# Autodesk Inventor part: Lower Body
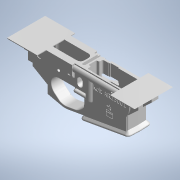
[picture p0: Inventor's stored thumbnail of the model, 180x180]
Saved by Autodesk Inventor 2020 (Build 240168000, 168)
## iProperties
Created: 2013-05
Part Number: Lower Body
Material: Generic
Document SubType Name: Modeling
Designer: johne
Appearance: Generic
Sending System: ACIS
Title: C:\Documents and Settings\Administrator\My Documents\AR-15 - Lower Receiver V5.1gs_main.STEP.stp
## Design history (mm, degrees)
feature "Base1"
sketch "Sketch1"
  geometry: L1 (0.067, -1.29)-(49.474, -1.29); L2 (49.474, -1.29)-(49.474, -38.649); L3 (49.474, -38.649)-(0.067, -38.649); L4 (0.067, -38.649)-(0.067, -1.29); L5 (49.818, 14.031)-(58.708, 14.031); L6 (58.708, 14.031)-(58.708, 4.735); C1 r 3.175 at (58.708, 4.735)
  constraints: 4 end point, 1 centre point, 1 coincident, 1 horizontal, 1 perpendicular, 2 other
  dimensions: "d0" = 6.35 diameter of C1
extrude "Extrusion1" cut sketch "Sketch1" distance "d1" = 50.8; taper "d2" = 0 deg
sketch "Sketch2"
  geometry: L1 (0.067, -1.29)-(49.474, -1.29); L2 (49.474, -1.29)-(49.474, -38.649); L3 (49.474, -38.649)-(0.067, -38.649); L4 (0.067, -38.649)-(0.067, -1.29); L5 (49.818, 14.031)-(58.708, 14.031); L6 (58.708, 14.031)-(58.708, 4.735); C1 r 3.175 at (58.708, 4.735); 1 further point
  constraints: 4 end point, 1 centre point, 1 coincident, 1 horizontal, 1 perpendicular, 2 other
  dimensions: "d3" = 6.35 diameter of C1
extrude "Extrusion2" cut sketch "Sketch2" distance "d4" = 0.508; taper "d5" = 0 deg
sketch "Sketch3"
  geometry: L1 (0.083, 0.318)-(7.097, 0.318) reference; L2 (0.083, 0.318)-(15.323, 0.319); L3 (15.323, 0.319)-(15.323, -13.778); L4 (-1.74, -48.939)-(-1.74, -29.698) reference; L5 (15.323, -13.778)-(-1.74, -29.698); L6 (-1.74, -29.698)-(0.083, 0.318); C1 r 3.175 at (7.097, -6.045) reference; 1 further point
  constraints: 8 end point, 1 vertical
  dimensions: "d6" = 15.24 distance of L1.start L2.end; "d7" = 14.097 distance of L2.end L3.end
extrude "Extrusion3" join sketch "Sketch3" stored distance "d8" = 0.508; taper "d9" = 0 deg
sketch "Sketch5"
  geometry: L1 (6.987, 0.318)-(-8.253, 0.319) reference; L2 (-8.253, 0.319)-(-8.253, -13.778) reference; L3 (-8.253, -13.778)-(6.645, -27.678) reference; L4 (9.518, -48.986)-(9.518, 0.318) reference; L5 (9.518, 0.318)-(-8.253, 0.319); L6 (-8.253, 0.319)-(-8.253, -13.778) reference; L7 (-8.253, -13.778)-(10.788, -31.542); L8 (10.788, 0.318)-(10.788, -50.5) reference; L9 (10.788, -31.542)-(10.788, 0.318); L10 (10.788, 0.318)-(-8.253, 0.319); L11 (6.324, -26.023)-(6.324, 0.318) reference; L12 (6.987, 0.318)-(6.324, 0.318) reference; L13 (6.987, 0.318)-(-8.253, 0.319) reference; L14 (-8.253, 0.319)-(-8.253, -13.778) reference; L15 (-8.253, -13.778)-(6.645, -27.678) reference; L16 (6.645, -26.562)-(6.645, -27.678) reference; L17 (6.324, -26.023)-(6.645, -26.562) reference; L18 (6.324, 0.318)-(6.324, -27.378); L19 (6.324, -47.042)-(6.324, -26.023) reference; C1 r 3.175 at (-0.026, -6.045) reference; C2 r 3.175 at (-0.026, -6.045) reference; 1 further point
  constraints: 10 end point, 2 point on line, 1 parallel
extrude "Extrusion4" join sketch "Sketch5" stored distance "d10" = 0.508; taper "d11" = 0 deg
sketch "Sketch7"
  geometry: L1 (-0.686, 21.608)-(-8.623, 21.608) reference; L2 (1.27, 49.304)-(-0.686, 49.304); L3 (-0.686, 49.304)-(-0.686, 21.608); L4 (-0.686, 21.608)-(1.27, 21.608); L5 (1.27, 21.608)-(1.27, 49.304); 1 further point
  constraints: 8 end point, 2 parallel, 1 horizontal, 1 perpendicular
extrude "Extrusion5" join sketch "Sketch7" stored distance "d12" = 0.508; taper "d13" = 0 deg
sketch "Sketch8"
  geometry: L1 (79.678, 27.031)-(75.901, 27.031); L2 (75.901, 27.031)-(75.901, 28.845); L3 (75.901, 28.845)-(79.678, 28.845); L4 (79.678, 28.845)-(79.678, 27.031); 1 further point
  constraints: 8 end point, 2 parallel, 1 horizontal, 1 perpendicular
extrude "Extrusion6" join sketch "Sketch8" distance "d14" = 0.508; taper "d15" = 0 deg
sketch "Sketch9"
  geometry: L1 (0, 21.608)-(0, 49.304) reference; L2 (0, 49.304)-(-1.27, 49.304) reference; L3 (-1.27, 49.304)-(-1.27, 21.608) reference; L4 (-1.27, 21.608)-(0, 21.608) reference; 1 further point
extrude "Extrusion7" join sketch "Sketch9" distance "d16" = 2.54; taper "d17" = 0 deg
sketch "Sketch10"
  geometry: L1 (14.577, 13.6)-(0, 0) reference; L2 (0, 0)-(14.577, 0) reference; L3 (14.577, 0)-(14.577, 13.6) reference; C1 r 3.175 at (6.35, 21.333) reference; 1 further point
extrude "Extrusion8" cut sketch "Sketch10" distance "d18" = 25.4; taper "d19" = 0 deg
fillet "Fillet1" dims "d20" = 1.27
sketch "Sketch11"
  geometry: L1 (0, 0)-(2.388, 0) reference; L2 (2.388, 0)-(2.388, 4.596) reference; L3 (2.388, 4.596)-(0, 4.596) reference; L4 (0, 0)-(0, 4.596) reference; L5 (9.523, 4.596)-(-5.763, 4.596) reference; L6 (6.149, -5.364)-(-3.569, -5.364); L7 (-3.569, -5.364)-(-3.569, 4.596); L8 (-3.569, 4.596)-(6.149, 4.596); L9 (6.149, 4.596)-(6.149, -5.364); 1 further point
  constraints: 8 end point, 2 parallel, 1 horizontal, 1 perpendicular, 1 point on line
extrude "Extrusion9" cut sketch "Sketch11" distance "d21" = 2.54; taper "d22" = 0 deg
sketch "Sketch12"
  geometry: L1 (33.211, 0.39)-(47.71, 0.39); L2 (47.71, 0.39)-(47.71, -9.066); L3 (47.71, -9.066)-(33.211, -9.066); L4 (33.211, -9.066)-(33.211, 0.39); L5 (31.497, -1.711)-(45.904, -1.711); L6 (45.904, -1.711)-(45.904, -7.52); L7 (45.904, -7.52)-(31.497, -7.52); L8 (31.497, -7.52)-(31.497, -1.711); 1 further point
  constraints: 8 end point, 2 parallel, 1 horizontal, 1 perpendicular, 2 other
extrude "Extrusion10" join sketch "Sketch12" distance "d23" = 1.016; taper "d24" = 0 deg
sketch "Sketch13"
  geometry: L1 (45.501, -1.483)-(67.918, -1.483); L2 (67.918, -1.483)-(67.918, -7.773); L3 (67.918, -7.773)-(45.501, -7.773); L4 (45.501, -7.773)-(45.501, -1.483); A1 r 10.362 centre (55.663, -18.136) between (64.101, -12.12) and (47.226, -12.12) reference; 1 further point
  constraints: 8 end point, 2 parallel, 1 horizontal, 1 perpendicular
extrude "Extrusion11" join sketch "Sketch13" distance "d25" = 1.016; taper "d26" = 0 deg
sketch "Sketch14"
  geometry: L1 (30.031, -0.213)-(52.828, -0.213); L2 (52.828, -0.213)-(52.828, -7.716); L3 (52.828, -7.716)-(30.031, -7.716); L4 (30.031, -7.716)-(30.031, -0.213); 1 further point
  constraints: 2 other
sketch "Sketch15"
  geometry: L1 (44.289, -4.551)-(70.126, -4.551); L2 (70.126, -4.551)-(70.126, -9.234); L3 (70.126, -9.234)-(44.289, -9.234); L4 (44.289, -9.234)-(44.289, -4.551); A1 r 10.362 centre (55.663, -18.136) between (64.101, -12.12) and (47.226, -12.12) reference; 1 further point
  constraints: 2 other
extrude "Extrusion12" cut sketch "Sketch14" distance "d27" = 1.016; taper "d28" = 0 deg
extrude "Extrusion13" cut sketch "Sketch15" distance "d29" = 1.016; taper "d30" = 0 deg
sketch "Sketch16"
  geometry: L1 (18.123, 4.596)-(-2.134, 4.596) reference; L2 (-2.134, 4.596)-(8.974, 4.596); L3 (8.974, 4.596)-(8.974, -7.604); L4 (8.974, -7.604)-(-2.134, -7.604); L5 (-2.134, -7.604)-(-2.134, 4.596); 1 further point
  constraints: 8 end point, 2 parallel, 1 horizontal, 1 perpendicular
extrude "Extrusion14" cut sketch "Sketch16" stored distance "d31" = 1.016; taper "d32" = 0 deg
sketch "Sketch19"
  geometry: L1 (0.426, -10.923)-(49.548, -10.923); L2 (49.548, -10.923)-(49.548, -43.999); L3 (49.548, -43.999)-(0.426, -43.999); L4 (0.426, -43.999)-(0.426, -10.923); L5 (20.374, -24.214)-(24.084, -24.214); L6 (24.084, -24.214)-(24.852, -25.164); L7 (24.852, -25.164)-(29.633, -25.164); L8 (29.633, -31.769)-(20.374, -31.769); L9 (23.426, -21.87)-(24.04, -19.818); L10 (24.418, -18.549)-(25.032, -16.496); L11 (22.277, -18.6)-(24.418, -18.549); L12 (25.742, -18.517)-(27.884, -18.466); L13 (26.892, -21.788)-(26.181, -19.766); L14 (25.742, -18.517)-(25.032, -16.496); L15 (27.884, -18.466)-(26.181, -19.766); L16 (25.129, -20.57)-(23.426, -21.87); L17 (26.892, -21.788)-(25.129, -20.57); L18 (24.04, -19.818)-(22.277, -18.6); L19 (25.002, -15.264)-(24.133, -18.175); L20 (24.133, -18.175)-(21.095, -18.247); L21 (21.095, -18.247)-(23.595, -19.974); L22 (23.595, -19.974)-(22.726, -22.885); L23 (22.726, -22.885)-(25.14, -21.041); L24 (25.14, -21.041)-(27.64, -22.767); L25 (27.64, -22.767)-(26.632, -19.901); L26 (26.632, -19.901)-(29.047, -18.057); L27 (29.047, -18.057)-(26.01, -18.13); L28 (26.01, -18.13)-(25.002, -15.264); L29 (30.014, -24.783)-(25.034, -24.783); L30 (25.034, -24.783)-(24.266, -23.833); L31 (24.266, -23.833)-(19.993, -23.833); L32 (19.993, -23.833)-(19.993, -32.15); L33 (19.993, -32.15)-(30.014, -32.15); L34 (30.014, -32.15)-(30.014, -24.783); L35 (20.374, -26.98)-(29.633, -26.98); L36 (29.633, -26.467)-(20.374, -26.467); L37 (29.633, -25.164)-(29.633, -26.467); L38 (29.633, -26.98)-(29.633, -31.769); L39 (20.374, -31.769)-(20.374, -26.98); L40 (20.374, -26.467)-(20.374, -24.214); 2 further points; 1 other entity
  constraints: 72 end point, 9 perpendicular, 3 parallel, 2 vertical, 1 horizontal, 19 other
  dimensions: "d152" = 0.381 distance between parallel lines of L14 L28; "d153" = 0.381 distance between parallel lines of L7 L29
extrude "Extrusion15" cut sketch "Sketch19" distance "d156" = 0.508; taper "d157" = 0 deg
sketch "Sketch20"
  geometry: L1 (-68.913, 58.342)-(-68.913, 45.515) reference; L2 (-68.913, 45.515)-(-54.337, 31.916) reference; L3 (-54.337, 31.916)-(-49.873, 31.916) reference; L4 (-49.873, 31.916)-(-49.873, 8.794) reference; L5 (0, 0)-(-49.873, 8.794) reference; L6 (0, 0)-(0, 35.799) reference; L7 (-1.657, 35.799)-(0, 35.799) reference; L8 (-1.657, 42.149)-(0, 42.149) reference; L9 (0, 42.149)-(0, 52.114) reference; L10 (0, 52.114)-(-2.483, 52.114) reference; L11 (-2.483, 52.114)-(-2.483, 56.804) reference; L12 (-2.483, 56.804)-(0, 56.804) reference; L13 (0, 56.804)-(0, 59.611) reference; L14 (0, 59.611)-(-67.694, 59.611) reference; L15 (-16.347, 26.543)-(-17.331, 26.543) reference; L16 (-17.331, 26.543)-(-17.331, 29.718) reference; L17 (-17.331, 29.718)-(-16.69, 29.718) reference; L18 (-21.157, 29.393)-(-21.849, 29.393) reference; L19 (-21.849, 29.393)-(-21.849, 29.718) reference; L20 (-21.849, 29.718)-(-20.18, 29.718) reference; L21 (-20.18, 29.718)-(-20.18, 29.393) reference; L22 (-20.18, 29.393)-(-20.872, 29.393) reference; L23 (-20.872, 29.393)-(-20.872, 26.543) reference; L24 (-20.872, 26.543)-(-21.157, 26.543) reference; L25 (-21.157, 26.543)-(-21.157, 29.393) reference; L26 (-26.856, 26.543)-(-26.856, 29.718) reference; L27 (-26.856, 29.718)-(-26.236, 29.718) reference; L28 (-25.997, 26.543)-(-26.856, 26.543) reference; L29 (-30.641, 26.543)-(-30.641, 29.718) reference; L30 (-30.641, 29.718)-(-30.006, 29.718) reference; L31 (-29.773, 28.009)-(-28.606, 26.543) reference; L32 (-28.606, 26.543)-(-28.958, 26.543) reference; L33 (-28.958, 26.543)-(-30.125, 28.009) reference; L34 (-30.125, 28.009)-(-30.356, 28.009) reference; L35 (-30.356, 28.009)-(-30.356, 26.543) reference; L36 (-30.356, 26.543)-(-30.641, 26.543) reference; L37 (-34.956, 27.156)-(-34.688, 27.317) reference; L38 (-33.124, 29.262)-(-33.382, 29.067) reference; L39 (-38.002, 26.543)-(-38.986, 26.543) reference; L40 (-38.986, 26.543)-(-38.986, 29.718) reference; L41 (-38.986, 29.718)-(-38.345, 29.718) reference; L42 (-25.96, 33.447)-(-25.692, 33.608) reference; L43 (-24.129, 35.554)-(-24.386, 35.359) reference; L44 (-31.252, 32.835)-(-31.252, 36.01) reference; L45 (-31.252, 36.01)-(-29.461, 36.01) reference; L46 (-29.461, 36.01)-(-29.461, 35.684) reference; L47 (-29.461, 35.684)-(-30.967, 35.684) reference; L48 (-30.967, 35.684)-(-30.967, 34.707) reference; L49 (-30.967, 34.707)-(-29.461, 34.707) reference; L50 (-29.461, 34.707)-(-29.461, 34.382) reference; L51 (-29.461, 34.382)-(-30.967, 34.382) reference; L52 (-30.967, 34.382)-(-30.967, 33.161) reference; L53 (-30.967, 33.161)-(-29.461, 33.161) reference; L54 (-29.461, 33.161)-(-29.461, 32.835) reference; L55 (-29.461, 32.835)-(-31.252, 32.835) reference; L56 (-35.73, 32.835)-(-35.73, 36.01) reference; L57 (-35.73, 36.01)-(-33.939, 36.01) reference; L58 (-33.939, 36.01)-(-33.939, 35.684) reference; L59 (-33.939, 35.684)-(-35.445, 35.684) reference; L60 (-35.445, 35.684)-(-35.445, 34.707) reference; L61 (-35.445, 34.707)-(-33.939, 34.707) reference; L62 (-33.939, 34.707)-(-33.939, 34.382) reference; L63 (-33.939, 34.382)-(-35.445, 34.382) reference; L64 (-35.445, 34.382)-(-35.445, 33.161) reference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; C1 r 3.175 at (-60.687, 53.248) reference; C2 r 1.5 at (-60.687, 53.248); A1 r 1.27 centre (-67.643, 58.342) between (-67.694, 59.611) and (-68.913, 58.342) reference; A2 r 6.35 centre (-7.156, 38.974) between (-12.864, 36.191) and (-1.657, 35.799) reference; A3 r 3.175 centre (-11.335, 38.974) between (-12.864, 41.756) and (-12.864, 36.191) reference; A4 r 6.35 centre (-7.156, 38.974) between (-1.657, 42.149) and (-12.864, 41.756) reference; 44 further points
  constraints: 1 centre point, 1 coincident, 53 other
  dimensions: "d162" = 3 diameter of C2
  node "Projected Loop10"
sketch "Sketch21"
  geometry: L1 (0.083, 1.587)-(14.053, 1.588) reference; L2 (0.064, 1.27)-(0.083, 1.587) reference; L3 (0.064, 1.27)-(0, 1.27) reference; L4 (0, 1.27)-(0, 0) reference; L5 (0, 0)-(3.352, 0) reference; L6 (3.414, -0.166)-(3.414, -13.807) reference; L7 (0, -26.005)-(0.1, -25.838) reference; L8 (0, -26.805)-(0, -26.005) reference; L9 (15.323, -12.508)-(0, -26.805) reference; L10 (15.323, 0.318)-(15.323, -12.508) reference; C1 r 3.175 at (7.097, -4.775) reference; C2 r 1.5 at (7.097, -4.775); A1 r 1.27 centre (14.053, 0.318) between (15.323, 0.318) and (14.053, 1.588) reference; A2 r 0.254 centre (3.16, -0.166) between (3.414, -0.166) and (3.352, 0) reference; A3 r 23.495 centre (-20.081, -13.807) between (0.1, -25.838) and (3.414, -13.807) reference; 1 further point
  constraints: 1 centre point, 1 coincident
  dimensions: "d165" = 3 diameter of C2
  node "Projected Loop11"
extrude "Extrusion18" join sketch "Sketch20" stored distance "d163" = 25.4; taper "d164" = 0 deg
extrude "Extrusion19" join sketch "Sketch21" stored distance "d166" = 25.4; taper "d167" = 0 deg
sketch "Sketch22"
  geometry: C1 r 3.188 at (-3.175, -6.35); A1 r 3.188 centre (-3.175, -6.35) between (0, -6.066) and (0, -6.634) reference; 1 further point
  constraints: 1 centre point, 1 coincident, 1 concentric
extrude "Extrusion20" cut sketch "Sketch22" distance "d168" = 76.2; taper "d169" = 0 deg
sketch "Sketch23"
  geometry: L1 (9.9, 6.635)-(9.9, 14.656) reference; L2 (10.535, 15.291)-(13.921, 15.291) reference; L3 (13.921, 15.291)-(13.921, 17.463) reference; L4 (0, 17.463)-(13.921, 17.463) reference; L5 (0, 14.656)-(0, 17.463) reference; L6 (0, 14.656)-(-4.07, 14.656) reference; L7 (-4.07, 14.656)-(-4.07, 9.966) reference; L8 (-4.07, 9.966)-(0, 9.966) reference; L9 (0, 0)-(0, 9.966) reference; L10 (0, 0)-(18.163, 0) reference; L11 (18.163, 3.581)-(18.163, 0) reference; L12 (13.921, 3.581)-(13.921, 5.704) reference; L13 (13.921, 5.704)-(10.535, 5.704) reference; L14 (-4.07, 9.966)-(0, 9.966) reference; L15 (-1.036, 9.966)-(-12.147, 9.966); L16 (-12.147, 9.966)-(-12.147, 14.656); L17 (-12.147, 14.656)-(-1.036, 14.656); L18 (-1.036, 14.656)-(-1.036, 9.966); A1 r 0.635 centre (10.535, 14.656) between (10.535, 15.291) and (9.9, 14.656) reference; A2 r 2.121 centre (16.042, 3.581) between (13.921, 3.581) and (18.163, 3.581) reference; 1 further point
  constraints: 8 end point, 2 parallel, 1 horizontal, 1 perpendicular, 1 point on line, 1 other
extrude "Extrusion21" cut sketch "Sketch23" stored distance "d171" = 76.2; taper "d172" = 0 deg
sketch "Sketch24"
  geometry: L1 (93.087, 30.531)-(93.087, 28.575) reference; L2 (25.394, 30.531)-(93.087, 30.531) reference; L3 (24.6, 29.369)-(24.6, 29.737) reference; L4 (23.806, 28.575)-(9.885, 28.575) reference; L5 (9.885, 28.575)-(9.885, 6.248) reference; L6 (5.643, 6.248)-(5.643, 28.156) reference; L7 (5.643, 28.156)-(0.723, 28.156) reference; L8 (0.215, 28.664)-(0.215, 32.854) reference; L9 (0.215, 32.854)-(-72.669, 32.854) reference; L10 (-72.669, 32.854)-(-72.669, 20.637) reference; L11 (-72.669, 20.637)-(-49.403, 20.637) reference; L12 (-2.407, 23.05)-(-44.821, 23.05) reference; L13 (3.15, 17.494)-(3.15, 11.081) reference; L14 (-2.407, 5.524)-(-44.073, 5.524) reference; L15 (-49.403, 9.512)-(-61.874, 9.512) reference; L16 (-72.669, 7.938)-(-65.75, 7.938) reference; L17 (-72.669, 7.938)-(-72.669, -4.279) reference; L18 (0, -4.279)-(-72.669, -4.279) reference; L19 (0, -4.279)-(0, 0) reference; L20 (77.498, 0)-(0, 0) reference; L21 (79.067, 1.346)-(79.067, 7.938) reference; L22 (79.067, 7.938)-(79.731, 7.938) reference; L23 (79.731, 7.938)-(79.731, 20.637) reference; L24 (79.731, 20.637)-(79.067, 20.637) reference; L25 (79.067, 28.575)-(79.067, 20.637) reference; L26 (79.678, 28.575)-(79.067, 28.575) reference; L27 (79.731, 28.575)-(79.678, 28.575) reference; L28 (93.087, 28.575)-(79.731, 28.575) reference; L29 (77.191, 24.105)-(77.191, 17.125) reference; L30 (77.191, 11.45)-(77.191, 4.47) reference; L31 (75.603, 2.883)-(69.317, 2.883) reference; L32 (69.317, 2.883)-(69.317, 2.438) reference; L33 (24.155, 2.438)-(69.317, 2.438) reference; L34 (24.155, 2.883)-(24.155, 2.438) reference; L35 (24.155, 2.883)-(17.869, 2.883) reference; L36 (16.281, 6.731)-(16.281, 4.47) reference; L37 (14.694, 8.319)-(13.932, 8.319) reference; L38 (12.344, 18.669)-(12.344, 9.906) reference; L39 (14.694, 20.256)-(13.932, 20.256) reference; L40 (16.281, 24.105)-(16.281, 21.844) reference; L41 (24.155, 25.692)-(17.869, 25.692) reference; L42 (24.155, 26.137)-(24.155, 25.692) reference; L43 (24.155, 26.137)-(26.34, 26.137) reference; L44 (26.34, 26.137)-(26.34, 26.422) reference; L45 (27.134, 27.216)-(37.865, 27.216) reference; L46 (38.659, 26.137)-(38.659, 26.422) reference; L47 (38.659, 26.137)-(69.317, 26.137) reference; L48 (69.317, 26.137)-(69.317, 25.692) reference; L49 (75.603, 25.692)-(69.317, 25.692) reference; L50 (69.444, 2.311)-(69.444, 2.756); L51 (69.444, 2.756)-(75.603, 2.756); L52 (77.318, 4.47)-(77.318, 11.397); L53 (77.318, 17.178)-(77.318, 24.105); L54 (75.603, 25.819)-(69.444, 25.819); L55 (69.444, 25.819)-(69.444, 26.264); L56 (69.444, 26.264)-(38.786, 26.264); L57 (38.786, 26.264)-(38.786, 26.422); L58 (37.865, 27.343)-(27.134, 27.343); L59 (26.213, 26.422)-(26.213, 26.264); L60 (26.213, 26.264)-(24.028, 26.264); L61 (24.028, 26.264)-(24.028, 25.819); L62 (24.028, 25.819)-(17.869, 25.819); L63 (16.154, 24.105)-(16.154, 21.844); L64 (14.694, 20.383)-(13.932, 20.383)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; A1 r 0.794 centre (25.394, 29.737) between (25.394, 30.531) and (24.6, 29.737) reference; A2 r 0.794 centre (23.806, 29.369) between (23.806, 28.575) and (24.6, 29.369) reference; A3 r 2.121 centre (7.764, 6.248) between (5.643, 6.248) and (9.885, 6.248) reference; A4 r 0.508 centre (0.723, 28.664) between (0.215, 28.664) and (0.723, 28.156) reference; A5 r 5.556 centre (-44.821, 17.494) between (-44.821, 23.05) and (-49.403, 20.637) reference; A6 r 5.556 centre (-2.407, 17.494) between (3.15, 17.494) and (-2.407, 23.05) reference; A7 r 5.556 centre (-2.407, 11.081) between (-2.407, 5.524) and (3.15, 11.081) reference; A8 r 5.556 centre (-44.073, 11.081) between (-49.403, 9.512) and (-44.073, 5.524) reference; A9 r 5.556 centre (-65.75, 13.494) between (-65.75, 7.938) and (-61.874, 9.512) reference; A10 r 1.587 centre (77.498, 1.587) between (77.498, 0) and (79.067, 1.346) reference; A11 r 3.969 centre (74.416, 14.287) between (77.191, 11.45) and (77.191, 17.125) reference; A12 r 1.587 centre (75.603, 4.47) between (75.603, 2.883) and (77.191, 4.47) reference; A13 r 1.587 centre (17.869, 4.47) between (16.281, 4.47) and (17.869, 2.883) reference; A14 r 1.587 centre (14.694, 6.731) between (16.281, 6.731) and (14.694, 8.319) reference; A15 r 1.587 centre (13.932, 9.906) between (12.344, 9.906) and (13.932, 8.319) reference; A16 r 1.587 centre (13.932, 18.669) between (13.932, 20.256) and (12.344, 18.669) reference; A17 r 1.587 centre (14.694, 21.844) between (14.694, 20.256) and (16.281, 21.844) reference; A18 r 1.587 centre (17.869, 24.105) between (17.869, 25.692) and (16.281, 24.105) reference; A19 r 0.794 centre (27.134, 26.422) between (27.134, 27.216) and (26.34, 26.422) reference; A20 r 0.794 centre (37.865, 26.422) between (38.659, 26.422) and (37.865, 27.216) reference; A21 r 1.587 centre (75.603, 24.105) between (77.191, 24.105) and (75.603, 25.692) reference; A22 r 1.714 centre (75.603, 4.47) between (75.603, 2.756) and (77.318, 4.47); A23 r 4.096 centre (74.416, 14.287) between (77.318, 11.397) and (77.318, 17.178); A24 r 1.714 centre (75.603, 24.105) between (77.318, 24.105) and (75.603, 25.819); A25 r 0.921 centre (37.865, 26.422) between (38.786, 26.422) and (37.865, 27.343); A26 r 0.921 centre (27.134, 26.422) between (27.134, 27.343) and (26.213, 26.422); A27 r 1.714 centre (17.869, 24.105) between (17.869, 25.819) and (16.154, 24.105); A28 r 1.461 centre (14.694, 21.844) between (14.694, 20.383) and (16.154, 21.844); A29 r 1.714 centre (13.932, 18.669) between (13.932, 20.383) and (12.217, 18.669); A30 r 1.714 centre (13.932, 9.906) between (12.217, 9.906) and (13.932, 8.192); A31 r 1.461 centre (14.694, 6.731) between (16.154, 6.731) and (14.694, 8.192); A32 r 1.714 centre (17.869, 4.47) between (16.154, 4.47) and (17.869, 2.756); 1 further point
  constraints: 42 end point, 22 point on circle, 11 centre point, 31 other
  dimensions: "d173" = 0.127 distance between parallel lines of L33 L70
extrude "Extrusion22" cut sketch "Sketch24" distance "d174" = 76.2; taper "d175" = 0 deg
sketch "Sketch25"
  geometry: C1 r 3.188 at (-60.687, 53.248); 1 further point
  constraints: 1 centre point, 1 coincident
  dimensions: "d176" = 6.3754 diameter of C1
extrude "Extrusion23" cut sketch "Sketch25" distance "d177" = 76.2; taper "d178" = 0 deg
sketch "Sketch26"
  geometry: L1 (-83.832, 39.513)-(-38.981, 39.513); L2 (-38.981, 39.513)-(-38.981, -17.608); L3 (-38.981, -17.608)-(-83.832, -17.608); L4 (-83.832, -17.608)-(-83.832, 39.513); L5 (104.222, 42.731)-(67.416, 42.731); L6 (67.416, 42.731)-(67.416, -14.591); L7 (67.416, -14.591)-(104.222, -14.591); L8 (104.222, -14.591)-(104.222, 42.731); 1 further point
  constraints: 16 end point, 4 parallel, 2 horizontal, 2 perpendicular
extrude "Extrusion24" join sketch "Sketch26" distance "d179" = 1; taper "d180" = 0 deg
sketch "Sketch27"
  geometry: L1 (-19.692, 26.543)-(-19.692, 29.718) reference; L2 (-19.692, 29.718)-(-17.901, 29.718) reference; L3 (-17.901, 29.718)-(-17.901, 29.393) reference; L4 (-17.901, 29.393)-(-19.407, 29.393) reference; L5 (-19.407, 29.393)-(-19.407, 28.416) reference; L6 (-19.407, 28.416)-(-17.901, 28.416) reference; L7 (-17.901, 28.416)-(-17.901, 28.09) reference; L8 (-17.901, 28.09)-(-19.407, 28.09) reference; L9 (-19.407, 28.09)-(-19.407, 26.869) reference; L10 (-19.407, 26.869)-(-17.901, 26.869) reference; L11 (-17.901, 26.869)-(-17.901, 26.543) reference; L12 (-17.901, 26.543)-(-19.692, 26.543) reference; L13 (-24.332, 27.801)-(-24.332, 29.718) reference; L14 (-24.332, 29.718)-(-24.047, 29.718) reference; L15 (-24.047, 29.718)-(-24.047, 27.816) reference; L16 (-22.582, 27.816)-(-22.582, 29.718) reference; L17 (-22.582, 29.718)-(-22.297, 29.718) reference; L18 (-22.297, 29.718)-(-22.297, 27.801) reference; L19 (-27.955, 26.543)-(-27.955, 29.718) reference; L20 (-27.955, 29.718)-(-27.67, 29.718) reference; L21 (-27.67, 29.718)-(-27.67, 26.543) reference; L22 (-27.67, 26.543)-(-27.955, 26.543) reference; L23 (-32.107, 29.393)-(-32.799, 29.393) reference; L24 (-32.799, 29.393)-(-32.799, 29.718) reference; L25 (-32.799, 29.718)-(-31.13, 29.718) reference; L26 (-31.13, 29.718)-(-31.13, 29.393) reference; L27 (-31.13, 29.393)-(-31.822, 29.393) reference; L28 (-31.822, 29.393)-(-31.822, 26.543) reference; L29 (-31.822, 26.543)-(-32.107, 26.543) reference; L30 (-32.107, 26.543)-(-32.107, 29.393) reference; L31 (-35.73, 26.543)-(-35.73, 29.718) reference; L32 (-35.73, 29.718)-(-35.445, 29.718) reference; L33 (-35.445, 29.718)-(-35.445, 26.543) reference; L34 (-35.445, 26.543)-(-35.73, 26.543) reference; L35 (-23.437, 32.835)-(-23.437, 36.01) reference; L36 (-23.437, 36.01)-(-21.646, 36.01) reference; L37 (-21.646, 36.01)-(-21.646, 35.684) reference; L38 (-21.646, 35.684)-(-23.152, 35.684) reference; L39 (-23.152, 35.684)-(-23.152, 34.707) reference; L40 (-23.152, 34.707)-(-21.646, 34.707) reference; L41 (-21.646, 34.707)-(-21.646, 34.382) reference; L42 (-21.646, 34.382)-(-23.152, 34.382) reference; L43 (-23.152, 34.382)-(-23.152, 33.161) reference; L44 (-23.152, 33.161)-(-21.646, 33.161) reference; L45 (-21.646, 33.161)-(-21.646, 32.835) reference; L46 (-21.646, 32.835)-(-23.437, 32.835) reference; L47 (-28.606, 32.835)-(-28.891, 32.835) reference; L48 (-28.891, 32.835)-(-28.891, 36.01) reference; L49 (-28.891, 36.01)-(-28.831, 36.01) reference; L50 (-28.831, 36.01)-(-26.734, 33.511) reference; L51 (-26.734, 33.511)-(-26.734, 36.01) reference; L52 (-26.734, 36.01)-(-26.449, 36.01) reference; L53 (-26.449, 36.01)-(-26.449, 32.835) reference; L54 (-26.449, 32.835)-(-26.514, 32.835) reference; L55 (-26.514, 32.835)-(-28.606, 35.328) reference; L56 (-28.606, 35.328)-(-28.606, 32.835) reference; L57 (-33.369, 32.835)-(-33.369, 36.01) reference; L58 (-33.369, 36.01)-(-31.822, 36.01) reference; L59 (-31.822, 36.01)-(-31.822, 35.684) reference; L60 (-31.822, 35.684)-(-33.084, 35.684) reference; L61 (-33.084, 35.684)-(-33.084, 34.707) reference; L62 (-33.084, 34.707)-(-31.822, 34.707) reference; L63 (-31.822, 34.707)-(-31.822, 34.382) reference; L64 (-31.822, 34.382)-(-33.084, 34.382) reference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; C1 r 3.188 at (-60.687, 53.248) reference; A1 r 1.27 centre (-67.643, 58.342) between (-68.885, 58.611) and (-68.913, 58.342) reference; A2 r 6.35 centre (-7.156, 38.974) between (-12.864, 36.191) and (-1.657, 35.799) reference; A3 r 3.175 centre (-11.335, 38.974) between (-12.864, 41.756) and (-12.864, 36.191) reference; A4 r 6.35 centre (-7.156, 38.974) between (-1.657, 42.149) and (-12.864, 41.756) reference; 43 further points
  constraints: 10 end point, 2 parallel, 2 point on line, 1 horizontal, 1 perpendicular, 53 other
extrude "Extrusion25" join sketch "Sketch27" stored distance "d181" = 1; taper "d182" = 0 deg
fillet "Fillet2" dims "d183" = 3.175
sketch "Sketch28"
  geometry: L1 (0, 23.063)-(0.336, 23.063) reference; L2 (0, 23.063)-(0, 0) reference; L3 (0.336, 0)-(0, 0) reference; L4 (2.051, 8.641)-(2.051, 1.714) reference; L5 (2.051, 21.349)-(2.051, 14.422) reference; A1 r 1.714 centre (0.336, 1.714) between (0.336, 0) and (2.051, 1.714) reference; A2 r 4.096 centre (-0.851, 11.532) between (2.051, 8.641) and (2.051, 14.422) reference; A3 r 1.714 centre (0.336, 21.349) between (2.051, 21.349) and (0.336, 23.063) reference; 1 further point
extrude "Extrusion26" cut sketch "Sketch28" distance "d184" = 25.4; taper "d185" = 0 deg
body "Solid1"
node "Projected Loop2"
node "Projected Loop5"
node "Projected Loop6"
node "Projected Loop7"
node "Projected Loop8"
node "Image4"
node "Reference1"
node "Projected Loop12"
node "Projected Loop13"
node "Projected Loop14"
node "Projected Loop15"
other parameters: "d48" = 0.381, "d90" = 0.635, "d95" = 0.635, "d96" = 0.635, "d97" = 0.635, "d98" = 0.635, "d99" = 0.635, "d100" = 0.635
